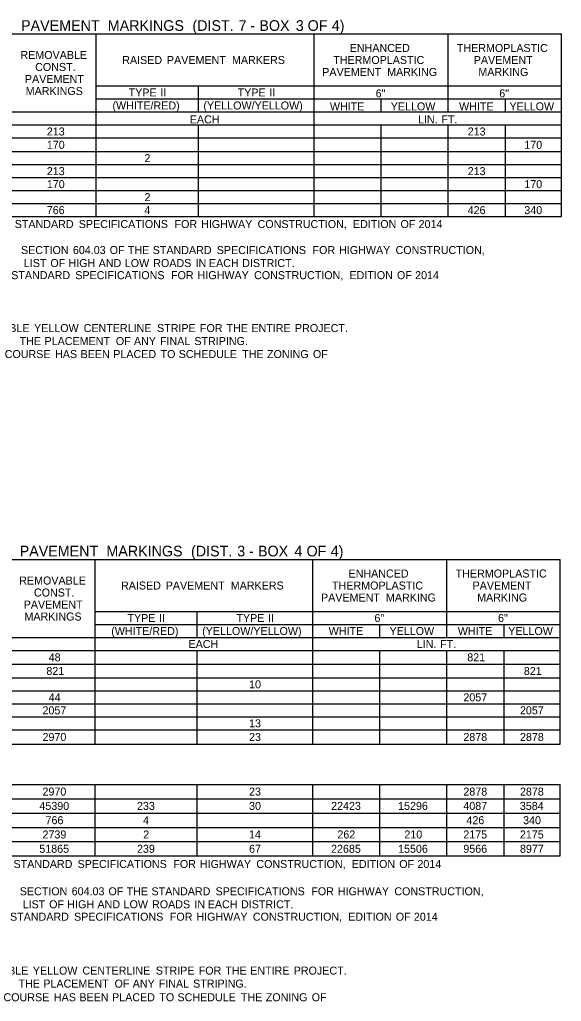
# Model space of a CAD drawing. Extents: x 540541 to 1930787, y -1948574 to 596640.
# Drawn here: x 542967 to 543373, y -1948443 to -1947707 of the extents above; entities that cross this region are included whole.
import ezdxf

# ---------------------------------------------------------------- set-up
doc = ezdxf.new("R2010")
doc.units = 0
doc.layers.add('Default', color=7, linetype='Continuous')

msp = doc.modelspace()

# ---------------------------------------------------------------- linework, layer by layer
at = {"layer": 'Default'}
for p, q in [((542613.14, -1947717.57), (543373.15, -1947717.57)), ((543024.59, -1947854.56), (543024.59, -1947717.57)), ((543187.9, -1947854.56), (543187.9, -1947717.57)), ((543288.32, -1947776.07), (543288.32, -1947717.57)), ((543373.15, -1947756.57), (543373.15, -1947717.57)), ((543024.59, -1947756.57), (543373.15, -1947756.57)), ((543101.12, -1947776.07), (543101.12, -1947756.57)), ((543288.32, -1947776.07), (543288.32, -1947756.57)), ((543373.15, -1947776.07), (543373.15, -1947756.57)), ((543024.59, -1947766.32), (543373.15, -1947766.32)), ((543238.11, -1947776.07), (543238.11, -1947766.32)), ((543331.22, -1947776.07), (543331.22, -1947766.32)), ((542846.65, -1947776.07), (543373.15, -1947776.07)), ((543373.15, -1947785.82), (543373.15, -1947776.07)), ((542613.14, -1947785.82), (543373.15, -1947785.82)), ((542786.69, -1947785.82), (543373.15, -1947785.82)), ((543024.59, -1947854.56), (543024.59, -1947785.82)), ((543101.12, -1947854.56), (543101.12, -1947785.82)), ((543101.12, -1947854.56), (543101.12, -1947785.82)), ((543187.9, -1947854.56), (543187.9, -1947785.82)), ((543238.11, -1947854.56), (543238.11, -1947785.82)), ((543238.11, -1947854.56), (543238.11, -1947785.82)), ((543288.32, -1947854.56), (543288.32, -1947785.82)), ((543288.32, -1947854.56), (543288.32, -1947785.82)), ((543331.22, -1947854.56), (543331.22, -1947785.82)), ((543331.22, -1947854.56), (543331.22, -1947785.82)), ((543373.15, -1947854.56), (543373.15, -1947785.82)), ((542786.69, -1947795.57), (543373.15, -1947795.57)), ((542786.69, -1947805.81), (543373.15, -1947805.81)), ((542613.14, -1947815.56), (543373.15, -1947815.56)), ((542786.69, -1947815.56), (543373.15, -1947815.56)), ((542786.69, -1947825.31), (543373.15, -1947825.31)), ((542786.69, -1947835.06), (543373.15, -1947835.06)), ((542613.14, -1947844.81), (543373.15, -1947844.81)), ((542613.14, -1947854.56), (543373.15, -1947854.56)), ((542612.22, -1948111.69), (543372.23, -1948111.69)), ((543023.67, -1948250.14), (543023.67, -1948111.69)), ((543186.98, -1948250.14), (543186.98, -1948111.69)), ((543287.41, -1948170.19), (543287.41, -1948111.69)), ((543372.23, -1948150.69), (543372.23, -1948111.69)), ((543023.67, -1948150.69), (543372.23, -1948150.69)), ((543100.21, -1948170.19), (543100.21, -1948150.69)), ((543287.41, -1948170.19), (543287.41, -1948150.69)), ((543372.23, -1948170.19), (543372.23, -1948150.69)), ((543023.67, -1948160.44), (543372.23, -1948160.44)), ((543237.2, -1948170.19), (543237.2, -1948160.44)), ((543330.31, -1948170.19), (543330.31, -1948160.44)), ((542845.73, -1948170.19), (543372.23, -1948170.19)), ((543372.23, -1948190.18), (543372.23, -1948170.19)), ((542612.22, -1948179.94), (543372.23, -1948179.94)), ((542785.77, -1948179.94), (543287.41, -1948179.94)), ((543023.67, -1948250.14), (543023.67, -1948179.94)), ((543100.21, -1948250.14), (543100.21, -1948179.94)), ((543100.21, -1948250.14), (543100.21, -1948179.94)), ((543186.98, -1948250.14), (543186.98, -1948179.94)), ((543237.2, -1948250.14), (543237.2, -1948179.94)), ((543237.2, -1948250.14), (543237.2, -1948179.94)), ((543287.41, -1948250.14), (543287.41, -1948179.94)), ((543287.41, -1948250.14), (543287.41, -1948179.94)), ((543330.31, -1948179.94), (543372.23, -1948179.94)), ((543330.31, -1948250.14), (543330.31, -1948179.94)), ((542785.77, -1948190.18), (543372.23, -1948190.18)), ((543372.23, -1948210.17), (543372.23, -1948190.18)), ((542785.77, -1948200.42), (543372.23, -1948200.42)), ((543330.31, -1948250.14), (543330.31, -1948200.42)), ((542612.22, -1948210.17), (543372.23, -1948210.17)), ((542785.77, -1948210.17), (543287.41, -1948210.17)), ((543330.31, -1948210.17), (543372.23, -1948210.17)), ((543372.23, -1948219.92), (543372.23, -1948210.17)), ((542785.77, -1948219.92), (543372.23, -1948219.92)), ((543372.23, -1948250.14), (543372.23, -1948219.92)), ((542785.77, -1948229.67), (543372.23, -1948229.67)), ((542612.22, -1948239.42), (543372.23, -1948239.42)), ((542612.22, -1948250.14), (543372.23, -1948250.14)), ((542612.22, -1948280.37), (543372.23, -1948280.37)), ((542612.22, -1948280.37), (543372.23, -1948280.37)), ((543023.67, -1948291.09), (543023.67, -1948280.37)), ((543023.67, -1948333.99), (543023.67, -1948280.37)), ((543100.21, -1948291.09), (543100.21, -1948280.37)), ((543100.21, -1948333.99), (543100.21, -1948280.37)), ((543186.98, -1948291.09), (543186.98, -1948280.37)), ((543186.98, -1948333.99), (543186.98, -1948280.37)), ((543237.2, -1948291.09), (543237.2, -1948280.37)), ((543237.2, -1948333.99), (543237.2, -1948280.37)), ((543287.41, -1948291.09), (543287.41, -1948280.37)), ((543287.41, -1948333.99), (543287.41, -1948280.37)), ((543330.31, -1948291.09), (543330.31, -1948280.37)), ((543330.31, -1948333.99), (543330.31, -1948280.37)), ((543372.23, -1948291.09), (543372.23, -1948280.37)), ((542612.22, -1948291.09), (543372.23, -1948291.09)), ((543372.23, -1948301.82), (543372.23, -1948291.09)), ((542612.22, -1948301.82), (543372.23, -1948301.82)), ((543023.67, -1948323.27), (543023.67, -1948301.82)), ((543100.21, -1948323.27), (543100.21, -1948301.82)), ((543186.98, -1948323.27), (543186.98, -1948301.82)), ((543237.2, -1948323.27), (543237.2, -1948301.82)), ((543287.41, -1948323.27), (543287.41, -1948301.82)), ((543330.31, -1948323.27), (543330.31, -1948301.82)), ((543372.23, -1948323.27), (543372.23, -1948301.82)), ((542612.22, -1948312.54), (543372.23, -1948312.54)), ((542612.22, -1948323.27), (543372.23, -1948323.27)), ((543372.23, -1948333.99), (543372.23, -1948323.27)), ((542612.22, -1948333.99), (543372.23, -1948333.99))]:
    msp.add_line(p, q, dxfattribs=at)

# ---------------------------------------------------------------- texts
for s, height, p in [(' PAVEMENT', 8, (542965.29, -1947715.24)), (' MARKINGS', 8, (543030.27, -1947715.24)), (' (DIST.', 8, (543093.69, -1947715.24)), (' 7', 8, (543128.31, -1947715.24)), (' BOX', 8, (543143.88, -1947715.24)), (' 3', 8, (543171.2, -1947715.24)), (' OF', 8, (543180.03, -1947715.24)), (' 4)', 8, (543198.14, -1947715.24)), (' -', 8, (543137.13, -1947715.24)), ('ENHANCED', 6, (543214.56, -1947731.07)), ('THERMOPLASTIC', 6, (543294.85, -1947731.07)), ('REMOVABLE', 6, (542967.79, -1947736.32)), ('CONST.', 6, (542978.81, -1947745.32)), ('RAISED', 6, (543044.09, -1947740.07)), (' PAVEMENT', 6, (543075.35, -1947740.07)), (' MARKERS', 6, (543124.09, -1947740.07)), ('THERMOPLASTIC', 6, (543202.23, -1947740.07)), ('PAVEMENT', 6, (543307.53, -1947740.07)), ('PAVEMENT', 6, (543193.97, -1947749.07)), (' MARKING', 6, (543240.38, -1947749.07)), ('MARKING', 6, (543310.97, -1947749.07)), ('PAVEMENT', 6, (542971.16, -1947754.32)), ('MARKINGS', 6, (542971.75, -1947763.32)), ('TYPE', 6, (543048.89, -1947764.45)), (' II', 6, (543070.38, -1947764.45)), ('TYPE', 6, (543130.55, -1947764.45)), (' II', 6, (543152.04, -1947764.45)), ('6"', 6, (543234, -1947765.12)), ('6"', 6, (543326.63, -1947765.12)), ('(WHITE/RED)', 6, (543036.76, -1947774.2)), ('(YELLOW/YELLOW)', 6, (543104.91, -1947774.2)), ('WHITE', 6, (543199.71, -1947774.87)), ('YELLOW', 6, (543245.29, -1947774.87)), ('WHITE', 6, (543296.48, -1947774.87)), ('YELLOW', 6, (543334.26, -1947774.87)), ('EACH', 6, (543094.69, -1947784.62)), ('LIN.', 6, (543265.74, -1947784.62)), (' FT.', 6, (543280.99, -1947784.62)), ('213', 6, (542987.56, -1947793.7)), ('213', 6, (543302.97, -1947793.7)), ('170', 6, (542987.57, -1947803.69)), ('170', 6, (543345.4, -1947803.69)), ('2', 6, (543060.75, -1947813.69)), ('213', 6, (542987.56, -1947823.44)), ('213', 6, (543302.97, -1947823.44)), ('170', 6, (542987.57, -1947833.19)), ('170', 6, (543345.4, -1947833.19)), ('2', 6, (543060.75, -1947842.94)), ('766', 6, (542987.52, -1947852.69)), ('4', 6, (543060.62, -1947852.69)), ('426', 6, (543302.93, -1947852.69)), ('340', 6, (543345.4, -1947852.69)), (' STANDARD', 6, (542961.28, -1947863.11)), (' SPECIFICATIONS', 6, (543009.28, -1947863.11)), (' FOR', 6, (543081.05, -1947863.11)), (' HIGHWAY', 6, (543100.96, -1947863.11)), (' CONSTRUCTION,', 6, (543143.28, -1947863.11)), (' EDITION', 6, (543214.73, -1947863.11)), (' OF', 6, (543250.37, -1947863.11)), (' 2014', 6, (543263.96, -1947863.11)), (' SECTION', 6, (542965.97, -1947882.61)), (' 604.03', 6, (543004.88, -1947882.61)), (' OF', 6, (543032.45, -1947882.61)), (' THE', 6, (543046.04, -1947882.61)), (' STANDARD', 6, (543064.69, -1947882.61)), (' SPECIFICATIONS', 6, (543112.69, -1947882.61)), (' FOR', 6, (543184.46, -1947882.61)), (' HIGHWAY', 6, (543204.37, -1947882.61)), (' CONSTRUCTION,', 6, (543246.69, -1947882.61)), (' LIST', 6, (542968.14, -1947892.36)), (' OF', 6, (542988, -1947892.36)), (' HIGH', 6, (543001.58, -1947892.36)), (' AND', 6, (543024.19, -1947892.36)), (' LOW', 6, (543043.78, -1947892.36)), (' ROADS', 6, (543065.1, -1947892.36)), (' IN', 6, (543096.81, -1947892.36)), (' EACH', 6, (543106.83, -1947892.36)), (' DISTRICT.', 6, (543131.78, -1947892.36)), (' STANDARD', 6, (542958.66, -1947901.44)), (' SPECIFICATIONS', 6, (543006.66, -1947901.44)), (' FOR', 6, (543078.43, -1947901.44)), (' HIGHWAY', 6, (543098.34, -1947901.44)), (' CONSTRUCTION,', 6, (543140.66, -1947901.44)), (' EDITION', 6, (543212.11, -1947901.44)), (' OF', 6, (543247.75, -1947901.44)), (' 2014', 6, (543261.34, -1947901.44)), (' DOUBLE', 6, (542939.41, -1947941.11)), (' YELLOW', 6, (542975.77, -1947941.11)), (' CENTERLINE', 6, (543012.94, -1947941.11)), (' STRIPE', 6, (543067.93, -1947941.11)), (' FOR', 6, (543100.09, -1947941.11)), (' THE', 6, (543120, -1947941.11)), (' ENTIRE', 6, (543138.65, -1947941.11)), (' PROJECT.', 6, (543171.28, -1947941.11)), (' THE', 6, (542964.97, -1947950.86)), (' PLACEMENT', 6, (542983.62, -1947950.86)), (' OF', 6, (543037.03, -1947950.86)), (' ANY', 6, (543050.61, -1947950.86)), (' FINAL', 6, (543070.12, -1947950.86)), (' STRIPING.', 6, (543095.91, -1947950.86)), (' COURSE', 6, (542953.78, -1947960.61)), (' HAS', 6, (542991.53, -1947960.61)), (' BEEN', 6, (543010.66, -1947960.61)), (' PLACED', 6, (543035.14, -1947960.61)), (' TO', 6, (543070.57, -1947960.61)), (' SCHEDULE', 6, (543084.16, -1947960.61)), (' THE', 6, (543131.7, -1947960.61)), (' ZONING', 6, (543150.35, -1947960.61)), (' OF', 6, (543184.75, -1947960.61)), (' (DIST.', 8, (543092.66, -1948109.35)), (' 4)', 8, (543197.34, -1948109.35)), (' PAVEMENT', 8, (542964.25, -1948109.35)), (' MARKINGS', 8, (543029.24, -1948109.35)), (' 3', 8, (543127.28, -1948109.35)), (' -', 8, (543136.11, -1948109.35)), (' BOX', 8, (543142.86, -1948109.35)), (' 4', 8, (543170.17, -1948109.35)), (' OF', 8, (543179.23, -1948109.35)), ('ENHANCED', 6, (543213.65, -1948125.19)), ('THERMOPLASTIC', 6, (543293.94, -1948125.19)), ('REMOVABLE', 6, (542966.87, -1948130.44)), ('RAISED', 6, (543043.17, -1948134.19)), (' PAVEMENT', 6, (543074.44, -1948134.19)), (' MARKERS', 6, (543123.18, -1948134.19)), ('THERMOPLASTIC', 6, (543201.31, -1948134.19)), ('PAVEMENT', 6, (543306.62, -1948134.19)), ('CONST.', 6, (542977.9, -1948139.44)), ('PAVEMENT', 6, (543193.05, -1948143.19)), (' MARKING', 6, (543239.47, -1948143.19)), ('MARKING', 6, (543310.05, -1948143.19)), ('PAVEMENT', 6, (542970.24, -1948148.44)), ('MARKINGS', 6, (542970.83, -1948157.44)), ('TYPE', 6, (543047.98, -1948158.57)), (' II', 6, (543069.46, -1948158.57)), ('TYPE', 6, (543129.64, -1948158.57)), (' II', 6, (543151.12, -1948158.57)), ('6"', 6, (543233.09, -1948158.57)), ('6"', 6, (543325.71, -1948158.57)), ('(WHITE/RED)', 6, (543035.85, -1948168.32)), ('(YELLOW/YELLOW)', 6, (543104, -1948168.32)), ('WHITE', 6, (543198.79, -1948168.32)), ('YELLOW', 6, (543244.38, -1948168.32)), ('WHITE', 6, (543295.56, -1948168.32)), ('YELLOW', 6, (543333.35, -1948168.32)), ('EACH', 6, (543093.77, -1948178.07)), ('LIN.', 6, (543264.82, -1948178.07)), (' FT.', 6, (543280.08, -1948178.07)), ('48', 6, (542988.97, -1948188.06)), ('821', 6, (543302.64, -1948188.06)), ('821', 6, (542987.23, -1948198.3)), ('821', 6, (543345.05, -1948198.3)), ('10', 6, (543139.14, -1948208.29)), ('44', 6, (542988.99, -1948218.04)), ('2057', 6, (543299.73, -1948218.04)), ('2057', 6, (542984.32, -1948227.79)), ('2057', 6, (543342.14, -1948227.79)), ('13', 6, (543139.13, -1948237.54)), ('2970', 6, (542984.33, -1948247.78)), ('23', 6, (543139.12, -1948247.78)), ('2878', 6, (543299.73, -1948247.78)), ('2878', 6, (543342.14, -1948247.78)), ('2970', 6, (542984.33, -1948288.73)), ('23', 6, (543139.12, -1948288.73)), ('2878', 6, (543299.73, -1948288.73)), ('2878', 6, (543342.14, -1948288.73)), ('45390', 6, (542982, -1948299.45)), ('233', 6, (543055.13, -1948299.45)), ('30', 6, (543139.14, -1948299.45)), ('22423', 6, (543200.62, -1948299.45)), ('15296', 6, (543250.8, -1948299.45)), ('4087', 6, (543299.72, -1948299.45)), ('3584', 6, (543342.05, -1948299.45)), ('766', 6, (542986.61, -1948310.18)), ('4', 6, (543059.71, -1948310.18)), ('426', 6, (543302.02, -1948310.18)), ('340', 6, (543344.49, -1948310.18)), ('2739', 6, (542984.32, -1948320.9)), ('2', 6, (543059.82, -1948320.9)), ('14', 6, (543139.03, -1948320.9)), ('262', 6, (543205.31, -1948320.9)), ('210', 6, (543255.52, -1948320.9)), ('2175', 6, (543299.67, -1948320.9)), ('2175', 6, (543342.08, -1948320.9)), ('51865', 6, (542981.92, -1948331.63)), ('239', 6, (543055.15, -1948331.63)), ('67', 6, (543139.12, -1948331.63)), ('22685', 6, (543200.57, -1948331.63)), ('15506', 6, (543250.8, -1948331.63)), ('9566', 6, (543299.69, -1948331.63)), ('8977', 6, (543342.14, -1948331.63)), (' STANDARD', 6, (542960.37, -1948343.03)), (' SPECIFICATIONS', 6, (543008.37, -1948343.03)), (' FOR', 6, (543080.14, -1948343.03)), (' HIGHWAY', 6, (543100.05, -1948343.03)), (' CONSTRUCTION,', 6, (543142.37, -1948343.03)), (' EDITION', 6, (543213.81, -1948343.03)), (' OF', 6, (543249.46, -1948343.03)), (' 2014', 6, (543263.04, -1948343.03)), (' SECTION', 6, (542965.05, -1948363.5)), (' 604.03', 6, (543003.96, -1948363.5)), (' OF', 6, (543031.54, -1948363.5)), (' THE', 6, (543045.12, -1948363.5)), (' STANDARD', 6, (543063.77, -1948363.5)), (' SPECIFICATIONS', 6, (543111.77, -1948363.5)), (' FOR', 6, (543183.54, -1948363.5)), (' HIGHWAY', 6, (543203.45, -1948363.5)), (' CONSTRUCTION,', 6, (543245.77, -1948363.5)), (' LIST', 6, (542967.22, -1948373.25)), (' OF', 6, (542987.08, -1948373.25)), (' HIGH', 6, (543000.67, -1948373.25)), (' AND', 6, (543023.28, -1948373.25)), (' LOW', 6, (543042.86, -1948373.25)), (' ROADS', 6, (543064.18, -1948373.25)), (' IN', 6, (543095.89, -1948373.25)), (' EACH', 6, (543105.92, -1948373.25)), (' DISTRICT.', 6, (543130.86, -1948373.25)), (' STANDARD', 6, (542957.75, -1948382.57)), (' SPECIFICATIONS', 6, (543005.75, -1948382.57)), (' FOR', 6, (543077.52, -1948382.57)), (' HIGHWAY', 6, (543097.43, -1948382.57)), (' CONSTRUCTION,', 6, (543139.75, -1948382.57)), (' EDITION', 6, (543211.19, -1948382.57)), (' OF', 6, (543246.84, -1948382.57)), (' 2014', 6, (543260.42, -1948382.57)), (' DOUBLE', 6, (542938.5, -1948422.98)), (' YELLOW', 6, (542974.85, -1948422.98)), (' CENTERLINE', 6, (543012.02, -1948422.98)), (' STRIPE', 6, (543067.01, -1948422.98)), (' FOR', 6, (543099.17, -1948422.98)), (' THE', 6, (543119.09, -1948422.98)), (' ENTIRE', 6, (543137.74, -1948422.98)), (' PROJECT.', 6, (543170.36, -1948422.98)), (' THE', 6, (542964.06, -1948432.73)), (' PLACEMENT', 6, (542982.7, -1948432.73)), (' OF', 6, (543036.11, -1948432.73)), (' ANY', 6, (543049.7, -1948432.73)), (' FINAL', 6, (543069.2, -1948432.73)), (' STRIPING.', 6, (543094.99, -1948432.73)), (' COURSE', 6, (542952.86, -1948442.97)), (' HAS', 6, (542990.62, -1948442.97)), (' BEEN', 6, (543009.75, -1948442.97)), (' PLACED', 6, (543034.22, -1948442.97)), (' TO', 6, (543069.65, -1948442.97)), (' SCHEDULE', 6, (543083.25, -1948442.97)), (' THE', 6, (543130.78, -1948442.97)), (' ZONING', 6, (543149.43, -1948442.97)), (' OF', 6, (543183.84, -1948442.97))]:
    msp.add_text(s, height=height, dxfattribs=at).set_placement(p)

doc.saveas('drawing.dxf')
